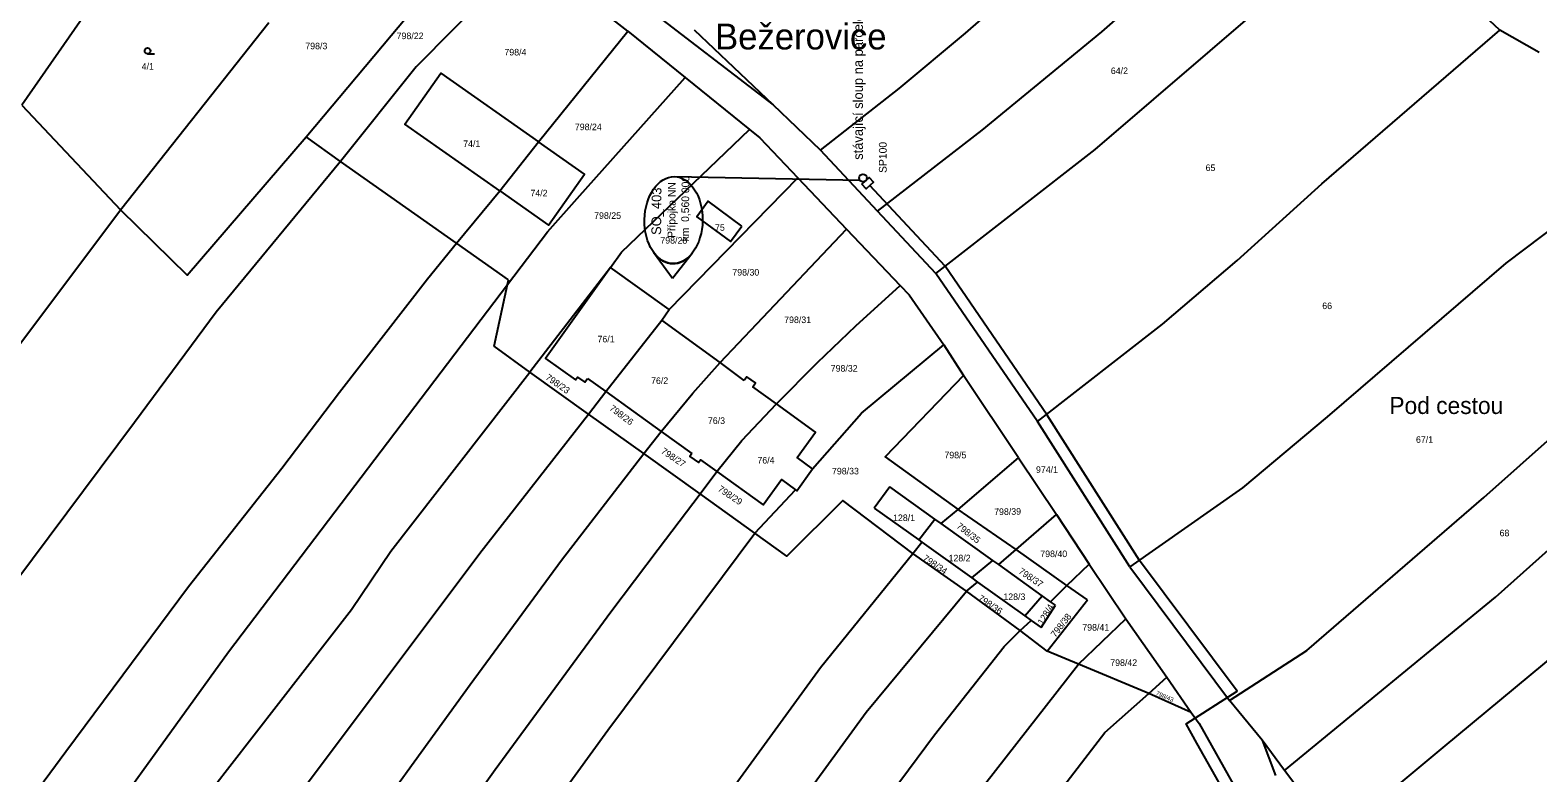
# Model space of a CAD drawing. Extents: x -7483133 to -743169, y -11317770 to -1127091.
# Drawn here: x -747897.9 to -747508.3, y -1131349.4 to -1131157.3 of the extents above; entities that cross this region are included whole.
import ezdxf

# ---------------------------------------------------------------- set-up
doc = ezdxf.new("R2010")
doc.units = 0
for name, color, linetype in [('_Násyp', 7, 'Continuous'), ('_TRASA_vedení kabelu_CEZ', 7, 'Continuous'), ('bublina_růžová_230_čára_tenká', 7, 'Continuous'), ('bublina_růžová_230_čára_tučná', 7, 'Continuous'), ('Default', 7, 'Continuous'), ('Hranice parcel', 7, 'Continuous'), ('Parcelní čísla', 7, 'Continuous'), ('Pop  PČ popisy', 7, 'Continuous'), ('Značky kultur', 7, 'Continuous')]:
    doc.layers.add(name, color=color, linetype=linetype)

msp = doc.modelspace()

# ---------------------------------------------------------------- linework, layer by layer
at = {"layer": '_TRASA_vedení kabelu_CEZ'}
msp.add_lwpolyline([(-747683.01, -1131197.18), (-747681.15, -1131195.45), (-747680.03, -1131196.64), (-747681.89, -1131198.38)], close=True, dxfattribs=at)
msp.add_lwpolyline([(-747599.82, -1131650.35), (-747590.15, -1131609.62), (-747577.85, -1131574.83), (-747576.11, -1131566), (-747573.02, -1131550.26), (-747574.14, -1131533.4), (-747574.33, -1131530.46), (-747575.58, -1131507.34), (-747576.38, -1131492.52), (-747578.4, -1131453.5), (-747579.22, -1131437.56), (-747579.88, -1131425.59), (-747579.54, -1131395.96), (-747581.01, -1131374.06), (-747586.67, -1131359.23), (-747588.9, -1131355.23), (-747596.45, -1131341.71), (-747599.17, -1131336.75), (-747586.05, -1131328.3), (-747611.25, -1131294.46), (-747635.1, -1131256.91), (-747661.52, -1131218.38), (-747680.96, -1131197.51)], dxfattribs=at)
at = {"layer": 'bublina_růžová_230_čára_tenká'}
msp.add_line((-747731.46, -1131195.21), (-747683.54, -1131196.12), dxfattribs=at)
at = {"layer": 'bublina_růžová_230_čára_tučná'}
for p, q in [((-747736.81, -1131214.78), (-747731.95, -1131221.46)), ((-747736.81, -1131214.78), (-747731.95, -1131221.46)), ((-747731.95, -1131221.46), (-747726.85, -1131214.97)), ((-747731.95, -1131221.46), (-747726.85, -1131214.97))]:
    msp.add_line(p, q, dxfattribs=at)
msp.add_ellipse((-747731.67, -1131206.46), major_axis=(0.21, 11.25), ratio=0.666667, dxfattribs=at)
msp.add_ellipse((-747731.67, -1131206.46), major_axis=(-0.21, -11.25), ratio=0.666473, start_param=5.557317, end_param=7.009053, dxfattribs=at)
at = {"layer": 'Default'}
msp.add_circle((-747682.72, -1131195.55), 1, dxfattribs=at)
msp.add_circle((-747682.72, -1131195.55), 1, dxfattribs=at)
at = {"layer": 'Hranice parcel'}
for p, q in [((-747826.65, -1131184.92), (-747779.57, -1131128.72)), ((-747743.52, -1131157.59), (-747769.22, -1131137.45)), ((-747518.15, -1131157.34), (-747534.94, -1131141.41)), ((-747874.56, -1131203.77), (-747836.24, -1131155.33)), ((-747766.58, -1131186.19), (-747743.52, -1131157.59)), ((-747743.52, -1131157.59), (-747728.7, -1131169.57)), ((-747705.95, -1131176.64), (-747726.24, -1131157.28)), ((-747508, -1131163.09), (-747518.15, -1131157.34)), ((-747728.7, -1131169.57), (-747712.03, -1131183.04)), ((-747900.11, -1131176.75), (-747874.56, -1131203.77)), ((-747693.71, -1131188.35), (-747705.95, -1131176.64)), ((-747817.77, -1131191.32), (-747826.65, -1131184.92)), ((-747776.59, -1131198.85), (-747766.58, -1131186.19)), ((-747678.94, -1131204.15), (-747693.71, -1131188.35)), ((-747787.74, -1131212.45), (-747817.77, -1131191.32)), ((-747732.77, -1131229.55), (-747699.59, -1131195.48)), ((-747699.59, -1131195.48), (-747686.96, -1131208.76)), ((-747787.74, -1131212.45), (-747776.59, -1131198.85)), ((-747663.87, -1131220.26), (-747678.94, -1131204.15)), ((-747686.96, -1131208.76), (-747673.07, -1131223.37)), ((-747774.35, -1131221.87), (-747787.74, -1131212.45)), ((-747747.94, -1131218.7), (-747768.78, -1131245.74)), ((-747732.77, -1131229.55), (-747747.94, -1131218.7)), ((-747778.06, -1131239.08), (-747774.62, -1131223.12)), ((-747774.62, -1131223.12), (-747774.35, -1131221.87)), ((-747637.6, -1131258.56), (-747663.87, -1131220.26)), ((-747734.74, -1131232.31), (-747732.77, -1131229.55)), ((-747749.21, -1131250.8), (-747734.74, -1131232.31)), ((-747719.59, -1131243.31), (-747734.74, -1131232.31)), ((-747768.78, -1131245.74), (-747778.06, -1131239.08)), ((-747661.79, -1131238.73), (-747656.71, -1131246.65)), ((-747713.41, -1131247.97), (-747719.59, -1131243.31)), ((-747753.62, -1131256.62), (-747768.78, -1131245.74)), ((-747642.55, -1131267.96), (-747656.71, -1131246.65)), ((-747753.92, -1131247.41), (-747749.21, -1131250.8)), ((-747753.62, -1131256.62), (-747749.21, -1131250.8)), ((-747749.21, -1131250.8), (-747734.88, -1131261.12)), ((-747739.39, -1131266.83), (-747753.62, -1131256.62)), ((-747613.72, -1131296.16), (-747637.6, -1131258.56)), ((-747739.39, -1131266.83), (-747734.88, -1131261.12)), ((-747734.88, -1131261.12), (-747726.94, -1131266.84)), ((-747724.81, -1131277.29), (-747739.39, -1131266.83)), ((-747658.09, -1131281.3), (-747642.55, -1131267.96)), ((-747642.55, -1131267.96), (-747632.73, -1131282.6)), ((-747724.81, -1131277.29), (-747720.46, -1131271.5)), ((-747710.63, -1131287.46), (-747724.81, -1131277.29)), ((-747710.63, -1131287.46), (-747700.19, -1131276.18)), ((-747675.77, -1131275.42), (-747679.79, -1131280.94)), ((-747664.12, -1131283.77), (-747675.77, -1131275.42)), ((-747679.79, -1131280.94), (-747668.32, -1131289.17)), ((-747662.52, -1131284.92), (-747658.09, -1131281.3)), ((-747643.16, -1131291.66), (-747658.09, -1131281.3)), ((-747668.32, -1131289.17), (-747664.12, -1131283.77)), ((-747662.52, -1131284.92), (-747664.12, -1131283.77)), ((-747649.2, -1131294.46), (-747662.52, -1131284.92)), ((-747643.16, -1131291.66), (-747632.73, -1131282.6)), ((-747632.73, -1131282.6), (-747624.26, -1131295.45)), ((-747669.82, -1131292.66), (-747667.48, -1131289.77)), ((-747668.32, -1131289.17), (-747667.48, -1131289.77)), ((-747667.48, -1131289.77), (-747654.61, -1131299)), ((-747656, -1131302.39), (-747669.82, -1131292.66)), ((-747647.65, -1131295.57), (-747643.16, -1131291.66)), ((-747630.05, -1131300.93), (-747643.16, -1131291.66)), ((-747654.61, -1131299), (-747649.2, -1131294.46)), ((-747647.65, -1131295.57), (-747649.2, -1131294.46)), ((-747636.4, -1131303.63), (-747647.65, -1131295.57)), ((-747630.05, -1131300.93), (-747624.26, -1131295.45)), ((-747624.26, -1131295.45), (-747614.76, -1131309.6)), ((-747613.72, -1131296.16), (-747587.97, -1131330.74)), ((-747656, -1131302.39), (-747653.1, -1131300.08)), ((-747654.61, -1131299), (-747653.1, -1131300.08)), ((-747653.1, -1131300.08), (-747640.91, -1131308.82)), ((-747634.28, -1131305.15), (-747630.05, -1131300.93)), ((-747624.72, -1131304.69), (-747630.05, -1131300.93)), ((-747642.09, -1131312.59), (-747656, -1131302.39)), ((-747640.91, -1131308.82), (-747636.4, -1131303.63)), ((-747634.28, -1131305.15), (-747636.4, -1131303.63)), ((-747635.14, -1131317.96), (-747624.72, -1131304.69)), ((-747632.97, -1131306.09), (-747634.28, -1131305.15)), ((-747640.91, -1131308.82), (-747639.3, -1131309.98)), ((-747636.7, -1131311.84), (-747632.97, -1131306.09)), ((-747627.04, -1131321.32), (-747614.76, -1131309.6)), ((-747614.76, -1131309.6), (-747604.21, -1131324.68)), ((-747642.09, -1131312.59), (-747639.3, -1131309.98)), ((-747635.14, -1131317.96), (-747642.09, -1131312.59)), ((-747639.3, -1131309.98), (-747636.7, -1131311.84)), ((-747627.04, -1131321.32), (-747635.14, -1131317.96)), ((-747608.88, -1131328.87), (-747627.04, -1131321.32)), ((-747608.88, -1131328.87), (-747604.21, -1131324.68)), ((-747604.21, -1131324.68), (-747597.93, -1131333.8)), ((-747597.93, -1131333.8), (-747608.88, -1131328.87)), ((-747579.59, -1131341), (-747587.97, -1131330.74)), ((-747573.75, -1131348.78), (-747579.59, -1131341)), ((-747579.59, -1131341), (-747576.14, -1131350.08)), ((-747560.74, -1131366.12), (-747573.75, -1131348.78))]:
    msp.add_line(p, q, dxfattribs=at)
for points in [[(-747693.71, -1131188.35), (-747673.39, -1131172.41), (-747656.27, -1131158.12), (-747617.7, -1131124.35), (-747583.1, -1131094.79)], [(-747678.94, -1131204.15), (-747651.91, -1131183.16), (-747620.97, -1131157.74), (-747567.13, -1131110.4)], [(-747663.87, -1131220.26), (-747622.68, -1131188.16), (-747577.82, -1131149.69), (-747551.23, -1131125.94)], [(-747866.49, -1131129.32), (-747883.09, -1131152.34), (-747900.11, -1131176.75)], [(-747764.01, -1131130.51), (-747750.16, -1131141.94), (-747739.59, -1131150.73), (-747705.95, -1131176.64)], [(-747769.22, -1131137.45), (-747798.15, -1131166.84), (-747817.77, -1131191.32)], [(-747637.6, -1131258.56), (-747605.36, -1131233.4), (-747586.04, -1131216.89), (-747564.17, -1131197.09), (-747518.15, -1131157.34)], [(-747776.59, -1131198.85), (-747801.07, -1131181.67), (-747791.81, -1131168.48), (-747766.58, -1131186.19)], [(-747774.62, -1131223.12), (-747764.24, -1131209.52), (-747756.55, -1131200.89), (-747728.7, -1131169.57)], [(-747874.56, -1131203.77), (-747857.38, -1131220.73), (-747826.65, -1131184.92)], [(-747747.94, -1131218.7), (-747745.11, -1131214.77), (-747712.03, -1131183.04)], [(-747712.03, -1131183.04), (-747709.37, -1131185.19), (-747699.59, -1131195.48)], [(-747776.59, -1131198.85), (-747763.95, -1131207.73), (-747754.69, -1131194.54), (-747766.58, -1131186.19)], [(-747817.77, -1131191.32), (-747849.87, -1131230.22), (-747870.95, -1131258.84), (-747919.45, -1131323.71), (-747970.67, -1131391.64), (-747999.11, -1131427.19), (-748029.39, -1131463.51), (-748052.97, -1131487.38)], [(-747478.68, -1131189), (-747516.61, -1131217.55), (-747562.75, -1131257.36), (-747584.62, -1131275.69), (-747613.72, -1131296.16)], [(-748069.53, -1131447.82), (-748039.5, -1131417.64), (-748010.54, -1131383.33), (-747969.15, -1131330.2), (-747939.35, -1131290.2), (-747874.56, -1131203.77)], [(-747714.02, -1131207.99), (-747722.72, -1131201.59), (-747725.64, -1131205.64), (-747716.93, -1131211.98), (-747714.02, -1131207.99)], [(-747719.59, -1131243.31), (-747710.17, -1131233.27), (-747686.96, -1131208.76)], [(-748039.41, -1131527.57), (-748021.11, -1131510.35), (-748001.42, -1131490.57), (-747960.37, -1131438.84), (-747946.8, -1131421.49), (-747906.82, -1131368.28), (-747888.73, -1131343.94), (-747857, -1131301.23), (-747832.91, -1131270.59), (-747818.02, -1131250.97), (-747795.27, -1131221.64), (-747787.74, -1131212.45)], [(-747747.94, -1131218.7), (-747764.72, -1131242.22), (-747757.01, -1131247.77), (-747756.49, -1131247.04), (-747754.62, -1131248.38), (-747753.92, -1131247.41)], [(-747587.97, -1131330.74), (-747567.99, -1131317.8), (-747522.26, -1131278.21), (-747503.48, -1131261.46), (-747452.5, -1131218.84)], [(-748030.59, -1131550.68), (-748006.8, -1131528.34), (-747986.12, -1131504.66), (-747956.18, -1131464.19), (-747938.32, -1131440.9), (-747892.39, -1131381.59), (-747846.71, -1131318.11), (-747774.62, -1131223.12)], [(-747705.1, -1131253.98), (-747694.48, -1131243.3), (-747684.57, -1131233.76), (-747673.07, -1131223.37)], [(-747673.07, -1131223.37), (-747670.79, -1131225.76), (-747661.79, -1131238.73)], [(-747695.74, -1131270.78), (-747683.08, -1131256.39), (-747661.79, -1131238.73)], [(-747573.75, -1131348.78), (-747519.29, -1131304), (-747475.75, -1131265.13), (-747451.48, -1131246.17), (-747439.12, -1131238.12)], [(-747734.88, -1131261.12), (-747726.72, -1131251.2), (-747719.59, -1131243.31)], [(-748020.54, -1131577.02), (-748001.95, -1131555.56), (-747973.86, -1131518.8), (-747960.03, -1131500.15), (-747932.73, -1131464.51), (-747901.57, -1131423.28), (-747883.06, -1131399.99), (-747885.07, -1131397.67), (-747846.34, -1131347.72), (-747814.92, -1131307.18), (-747804.7, -1131292.12), (-747768.78, -1131245.74)], [(-747705.1, -1131253.98), (-747711.22, -1131249.55), (-747710.52, -1131248.58), (-747712.71, -1131246.99), (-747713.41, -1131247.97)], [(-747656.71, -1131246.65), (-747676.97, -1131267.67), (-747658.09, -1131281.3)], [(-747720.46, -1131271.5), (-747714.03, -1131263.42), (-747705.1, -1131253.98)], [(-747695.74, -1131270.78), (-747699.76, -1131267.83), (-747695.01, -1131261.29), (-747705.1, -1131253.98)], [(-748006.35, -1131589.51), (-747976.31, -1131553.75), (-747942.87, -1131510.32), (-747895.09, -1131446.4), (-747868.39, -1131410.63), (-747869.95, -1131409.28), (-747831.18, -1131358.67), (-747781.73, -1131292.56), (-747753.62, -1131256.62)], [(-747560.74, -1131366.12), (-747532.83, -1131342.86), (-747438.82, -1131264.87), (-747425.11, -1131256.95)], [(-747991.94, -1131600.7), (-747981.03, -1131587.21), (-747950.23, -1131550.08), (-747903.91, -1131491.23), (-747862.5, -1131433.61), (-747817.95, -1131373.1), (-747784.2, -1131326.61), (-747760.62, -1131294.4), (-747739.39, -1131266.83)], [(-747726.94, -1131266.84), (-747727.47, -1131267.57), (-747725.23, -1131269.17), (-747724.71, -1131268.44), (-747720.46, -1131271.5)], [(-747720.46, -1131271.5), (-747708.48, -1131280.13), (-747703.77, -1131273.54), (-747700.19, -1131276.18)], [(-747700.19, -1131276.18), (-747699.8, -1131276.47), (-747695.74, -1131270.78)], [(-747972.95, -1131605.36), (-747952.16, -1131580.99), (-747925.8, -1131548.77), (-747894.55, -1131508.92), (-747869.95, -1131475.83), (-747822.94, -1131411.83), (-747777.73, -1131348.55), (-747747.86, -1131307.75), (-747735.67, -1131291.6), (-747724.81, -1131277.29)], [(-747669.82, -1131292.66), (-747687.96, -1131278.99), (-747702.43, -1131293.35), (-747710.63, -1131287.46)], [(-747953.56, -1131610.11), (-747936.63, -1131589.74), (-747927.22, -1131580.6), (-747917.02, -1131567.38), (-747880.11, -1131518.39), (-747857.18, -1131486.6), (-747811.82, -1131424.61), (-747784.23, -1131387.47), (-747748.68, -1131338.4), (-747710.63, -1131287.46)], [(-747915.42, -1131619.45), (-747873.23, -1131566.86), (-747843.82, -1131525.97), (-747806.53, -1131475.44), (-747778.43, -1131437.61), (-747729.49, -1131371.5), (-747693.71, -1131322.2), (-747669.82, -1131292.66)], [(-747895.76, -1131621.42), (-747861.58, -1131578.6), (-747835.67, -1131543.4), (-747806.42, -1131503.18), (-747795.07, -1131488.14), (-747755.24, -1131433.32), (-747715.49, -1131379.82), (-747681.87, -1131333.76), (-747656, -1131302.39)], [(-747879, -1131625.66), (-747851.66, -1131591.69), (-747829.65, -1131563.42), (-747808.64, -1131535.34), (-747757.65, -1131465.52), (-747713.97, -1131406.96), (-747691.09, -1131375.78), (-747664.28, -1131339.63), (-747646.2, -1131316.75), (-747642.09, -1131312.59)], [(-747860.06, -1131629.88), (-747832.75, -1131596.26), (-747816.97, -1131575.83), (-747776.82, -1131523.47), (-747762.78, -1131503.59), (-747734.31, -1131465.05), (-747710.2, -1131431.58), (-747690.98, -1131405.7), (-747669.96, -1131376.28), (-747627.04, -1131321.32)], [(-747842.01, -1131634.16), (-747811.79, -1131593.14), (-747801.87, -1131584.09), (-747752.07, -1131516.87), (-747707.12, -1131455.02), (-747691.23, -1131433.37), (-747676.82, -1131413.33), (-747658, -1131388.25), (-747620.26, -1131339), (-747608.88, -1131328.87)], [(-747597.93, -1131333.8), (-747595.82, -1131336.69), (-747586.28, -1131353.77)]]:
    msp.add_lwpolyline(points, dxfattribs=at)
at = {"layer": 'Značky kultur'}
msp.add_line((-747867.59, -1131163.43), (-747865.84, -1131163.43), dxfattribs=at)
msp.add_circle((-747867.59, -1131162.68), 0.75, dxfattribs=at)

# ---------------------------------------------------------------- texts
at = {"layer": '_Násyp'}
for s, height, p in [('km  0,560 000', 2, (-747727.71, -1131211.97)), ('SO_403', 2.5, (-747734.89, -1131210.3)), ('Přípojka NN', 2, (-747731.22, -1131211.06))]:
    msp.add_text(s, height=height, rotation=89.5821, dxfattribs=at).set_placement(p)
at = {"layer": '_TRASA_vedení kabelu_CEZ'}
for s, height, p in [('stávající sloup na parcele 64/1', 2.5, (-747682.75, -1131190.86)), ('SP100', 2, (-747676.6, -1131194.25))]:
    msp.add_text(s, height=height, rotation=90, dxfattribs=at).set_placement(p)
at = {"layer": 'Parcelní čísla'}
for s, p in [('798/3', (-747826.83, -1131162.27)), ('798/22', (-747803.22, -1131159.64)), ('798/4', (-747775.38, -1131163.86)), ('4/1', (-747869.11, -1131167.55)), ('64/2', (-747618.67, -1131168.68)), ('798/24', (-747757.18, -1131183.19)), ('74/1', (-747786.04, -1131187.55)), ('65', (-747594.18, -1131193.76)), ('74/2', (-747768.66, -1131200.32)), ('798/25', (-747752.19, -1131206.13)), ('75', (-747720.96, -1131209.21)), ('798/28', (-747735.08, -1131212.54)), ('798/30', (-747716.48, -1131220.8)), ('66', (-747564.03, -1131229.47)), ('798/31', (-747703.08, -1131233.09)), ('76/1', (-747751.33, -1131238.08)), ('76/2', (-747737.48, -1131248.84)), ('798/32', (-747691.06, -1131245.65)), ('76/3', (-747722.79, -1131259.17)), ('67/1', (-747539.82, -1131264.06)), ('798/5', (-747661.68, -1131268.07)), ('76/4', (-747710, -1131269.42)), ('798/33', (-747690.73, -1131272.23)), ('974/1', (-747638.01, -1131271.84)), ('128/1', (-747674.95, -1131284.3)), ('68', (-747518.21, -1131288.24)), ('128/2', (-747660.6, -1131294.73)), ('798/40', (-747636.9, -1131293.62)), ('128/3', (-747646.44, -1131304.73)), ('798/41', (-747626.04, -1131312.65)), ('798/42', (-747618.82, -1131321.77))]:
    msp.add_text(s, height=1.7, dxfattribs=at).set_placement(p)
for s, height, rotation, p in [('798/23', 1.7, 325, (-747764.93, -1131247.5)), ('798/26', 1.7, 323, (-747748.4, -1131255.45)), ('798/27', 1.7, 326, (-747735.05, -1131266.6)), ('798/29', 1.7, 326, (-747720.39, -1131276.39)), ('798/39', 1.7, 1, (-747648.81, -1131282.76)), ('798/35', 1.7, 322, (-747658.7, -1131285.91)), ('798/34', 1.7, 326, (-747667.43, -1131294.3)), ('798/37', 1.7, 326, (-747642.68, -1131297.68)), ('798/36', 1.7, 326, (-747653.17, -1131304.65)), ('128/4', 1.7, 59, (-747636.25, -1131311.3)), ('798/38', 1.7, 52, (-747633.01, -1131314.51)), ('798/43', 1.14, 336, (-747607.16, -1131329.21))]:
    msp.add_text(s, height=height, rotation=rotation, dxfattribs=at).set_placement(p)
at = {"layer": 'Pop  PČ popisy'}
for s, height, p in [('Bežerovice', 6.7, (-747720.95, -1131162.31)), ('Pod cestou', 4.4, (-747546.7, -1131256.6))]:
    msp.add_text(s, height=height, dxfattribs=at).set_placement(p)

doc.saveas('drawing.dxf')
